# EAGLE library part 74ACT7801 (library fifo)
FIFO
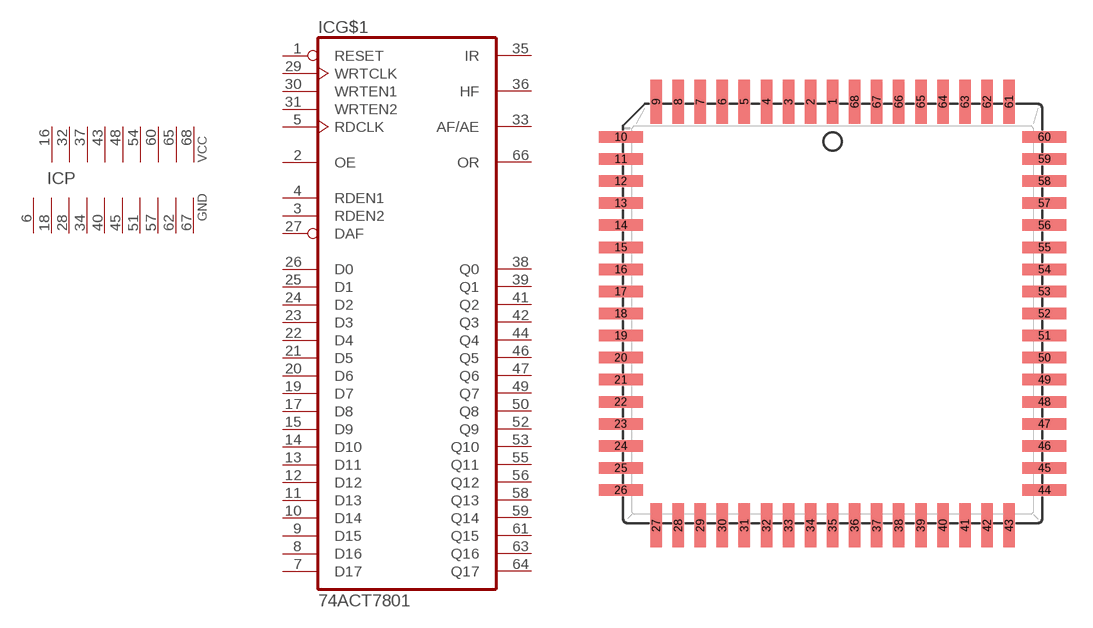
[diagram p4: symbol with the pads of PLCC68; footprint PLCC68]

Designator prefix IC; gates G$1=7801 P=9PWR10GN

## 74ACT7801 (MF: TEXAS INSTRUMENT CONNECTORS; MPN: SN74ACT7801-15FN; OC_FARNELL: unknown; OC_NEWARK: 08F5923)  [PLCC68]
1  G$1:RESET  in
2  G$1:OE  in
3  G$1:RDEN2  in
4  G$1:RDEN1  in
5  G$1:RDCLK  in
6  P:GND  pwr
7  G$1:D17  in
8  G$1:D16  in
9  G$1:D15  in
10  G$1:D14  in
11  G$1:D13  in
12  G$1:D12  in
13  G$1:D11  in
14  G$1:D10  in
15  G$1:D9  in
16  P:VCC  pwr
17  G$1:D8  in
18  P:GND  pwr
19  G$1:D7  in
20  G$1:D6  in
21  G$1:D5  in
22  G$1:D4  in
23  G$1:D3  in
24  G$1:D2  in
25  G$1:D1  in
26  G$1:D0  in
27  G$1:DAF  in
28  P:GND  pwr
29  G$1:WRTCLK  in
30  G$1:WRTEN1  in
31  G$1:WRTEN2  in
32  P:VCC  pwr
33  G$1:AF/AE  out
34  P:GND  pwr
35  G$1:IR  out
36  G$1:HF  out
37  P:VCC  pwr
38  G$1:Q0  out
39  G$1:Q1  out
40  P:GND  pwr
41  G$1:Q2  out
42  G$1:Q3  out
43  P:VCC  pwr
44  G$1:Q4  out
45  P:GND  pwr
46  G$1:Q5  out
47  G$1:Q6  out
48  P:VCC  pwr
49  G$1:Q7  out
50  G$1:Q8  out
51  P:GND  pwr
52  G$1:Q9  out
53  G$1:Q10  out
54  P:VCC  pwr
55  G$1:Q11  out
56  G$1:Q12  out
57  P:GND  pwr
58  G$1:Q13  out
59  G$1:Q14  out
60  P:VCC  pwr
61  G$1:Q15  out
62  P:GND  pwr
63  G$1:Q16  out
64  G$1:Q17  out
65  P:VCC  pwr
66  G$1:OR  out
67  P:GND  pwr
68  P:VCC  pwr

## Footprint PLCC68 (pad centres in mm)
Plastic Leaded Carrier Package
smd 0.66 x 2.54: 1 0,12.192; 2 -1.27,12.192; 3 -2.54,12.192; 4 -3.81,12.192; 5 -5.08,12.192; 6 -6.35,12.192; 7 -7.62,12.192; 8 -8.89,12.192; 9 -10.16,12.192; 27 -10.16,-12.192; 28 -8.89,-12.192; 29 -7.62,-12.192; 30 -6.35,-12.192; 31 -5.08,-12.192; 32 -3.81,-12.192; 33 -2.54,-12.192; 34 -1.27,-12.192; 35 0,-12.192; 36 1.27,-12.192; 37 2.54,-12.192; 38 3.81,-12.192; 39 5.08,-12.192; 40 6.35,-12.192; 41 7.62,-12.192; 42 8.89,-12.192; 43 10.16,-12.192; 61 10.16,12.192; 62 8.89,12.192; 63 7.62,12.192; 64 6.35,12.192; 65 5.08,12.192; 66 3.81,12.192; 67 2.54,12.192; 68 1.27,12.192
smd 2.54 x 0.66: 10 -12.192,10.16; 11 -12.192,8.89; 12 -12.192,7.62; 13 -12.192,6.35; 14 -12.192,5.08; 15 -12.192,3.81; 16 -12.192,2.54; 17 -12.192,1.27; 18 -12.192,0; 19 -12.192,-1.27; 20 -12.192,-2.54; 21 -12.192,-3.81; 22 -12.192,-5.08; 23 -12.192,-6.35; 24 -12.192,-7.62; 25 -12.192,-8.89; 26 -12.192,-10.16; 44 12.192,-10.16; 45 12.192,-8.89; 46 12.192,-7.62; 47 12.192,-6.35; 48 12.192,-5.08; 49 12.192,-3.81; 50 12.192,-2.54; 51 12.192,-1.27; 52 12.192,0; 53 12.192,1.27; 54 12.192,2.54; 55 12.192,3.81; 56 12.192,5.08; 57 12.192,6.35; 58 12.192,7.62; 59 12.192,8.89; 60 12.192,10.16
